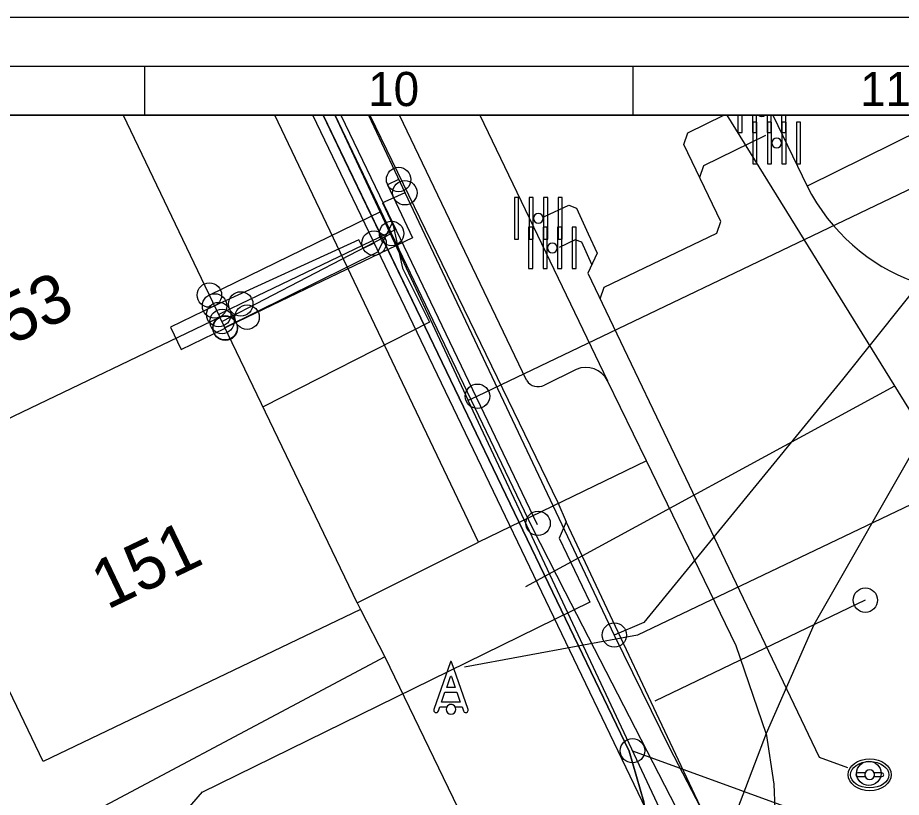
# Model space of a CAD drawing. Extents: x 192672 to 192910, y 446344 to 446512.
# Drawn here: x 192758.05 to 192776.14, y 446495.79 to 446511.76 of the extents above; entities that cross this region are included whole.
import ezdxf

# ---------------------------------------------------------------- set-up
doc = ezdxf.new("R2010")
doc.units = 0
for name, color, linetype in [('( Toegevoegd 29-11-2021 14_41_42) wegdeel vlak', 7, 'Continuous'), ('1010 viewport', 7, 'Continuous'), ('B-OI-KL-()_AFSLUITER_WATER-S', 7, 'Continuous'), ('B-OI-KL-()_OVERIG_RIOOLVRIJVERVAL-S', 7, 'Continuous'), ('B-OI-KL-()_PUNTVANLEVERING_WATER-S', 7, 'Continuous'), ('B-OI-KL-BUISLEIDING_OLIEGASCHEMICALIEN_GASLAGEDRUK-G', 7, 'Continuous'), ('B-OI-KL-DATA-G', 7, 'Continuous'), ('B-OI-KL-DATA_GTWP-S', 7, 'Continuous'), ('B-OI-KL-DATA_KABELBED-G', 7, 'Continuous'), ('B-OI-KL-DATA_MOF-S', 7, 'Continuous'), ('B-OI-KL-DATA_OVERIG-S', 7, 'Continuous'), ('B-OI-KL-ET_LS-G', 7, 'Continuous'), ('B-OI-KL-ET_LS_DELIVERYPOINT-S', 7, 'Continuous'), ('B-OI-KL-ET_LS_MOF-S', 7, 'Continuous'), ('B-OI-KL-GAS_LD_AFTAKZADEL-S', 7, 'Continuous'), ('B-OI-KL-GAS_LD_DELIVERYPOINT-S', 7, 'Continuous'), ('B-OI-KL-GAS_LD_EINDKAP-S', 7, 'Continuous'), ('B-OI-KL-GAS_LD_OVERGANGSSTUK-S', 7, 'Continuous'), ('B-OI-KL-GAS_LD_TSTUK-S', 7, 'Continuous'), ('B-OI-KL-WATER-G', 7, 'Continuous'), ('B-OI-RI-RIOOLVRIJVERVAL-G', 7, 'Continuous'), ('bovenleidingmast', 7, 'Continuous'), ('Default', 7, 'Continuous'), ('huisnummerreeks BGT', 7, 'Continuous'), ('inspectie-   rioolput', 7, 'Continuous'), ('kant open verharding', 7, 'Continuous'), ('kant verharding', 7, 'Continuous'), ('kolk', 7, 'Continuous'), ('pand op maaiveld vlak', 7, 'Continuous'), ('verkeerseiland - berm', 7, 'Continuous'), ('X-XX-AL-TEKENBLAD-S', 7, 'Continuous')]:
    doc.layers.add(name, color=color, linetype=linetype)

# ---------------------------------------------------------------- blocks, each defined once
blk = doc.blocks.new('B-OI-KL-GAS_LD_AFTAKZADEL-S')
at = {"layer": 'Default'}
blk.add_circle((0, 0), 0.25, dxfattribs=at)
blk = doc.blocks.new('B-OI-KL-GAS_LD_DELIVERYPOINT-S')
at = {"layer": 'Default'}
blk.add_circle((0, 0), 0.25, dxfattribs=at)
blk = doc.blocks.new('B-OI-KL-GAS_LD_EINDKAP-S')
at = {"layer": 'Default'}
blk.add_circle((0, 0), 0.25, dxfattribs=at)
blk = doc.blocks.new('B-OI-KL-GAS_LD_OVERGANGSSTUK-S')
at = {"layer": 'Default'}
blk.add_circle((0, 0), 0.25, dxfattribs=at)
blk = doc.blocks.new('B-OI-KL-GAS_LD_TSTUK-S')
at = {"layer": 'Default'}
blk.add_circle((0, 0), 0.25, dxfattribs=at)
blk = doc.blocks.new('B-OI-KL-ET_LS_DELIVERYPOINT-S')
at = {"layer": 'Default'}
blk.add_circle((0, 0), 0.25, dxfattribs=at)
blk = doc.blocks.new('B-OI-KL-ET_LS_MOF-S')
at = {"layer": 'Default'}
blk.add_circle((0, 0), 0.25, dxfattribs=at)
blk = doc.blocks.new('B-OI-KL-DATA_OVERIG-S')
at = {"layer": 'Default'}
blk.add_circle((0, 0), 0.25, dxfattribs=at)
blk = doc.blocks.new('B-OI-KL-()_OVERIG_RIOOLVRIJVERVAL-S')
at = {"layer": 'Default'}
blk.add_circle((0, 0), 0.25, dxfattribs=at)
blk = doc.blocks.new('B-OI-KL-()_AFSLUITER_WATER-S')
at = {"layer": 'Default'}
blk.add_circle((0, 0), 0.25, dxfattribs=at)
blk = doc.blocks.new('B-OI-KL-()_PUNTVANLEVERING_WATER-S')
at = {"layer": 'Default'}
blk.add_circle((0, 0), 0.25, dxfattribs=at)
blk = doc.blocks.new('B-OI-KL-DATA_GTWP-S')
at = {"layer": 'Default'}
blk.add_circle((0, 0), 0.25, dxfattribs=at)
blk = doc.blocks.new('B-OI-KL-DATA_MOF-S')
at = {"layer": 'Default'}
blk.add_circle((0, 0), 0.25, dxfattribs=at)

msp = doc.modelspace()

# ---------------------------------------------------------------- linework, layer by layer
at = {"layer": '( Toegevoegd 29-11-2021 14_41_42) wegdeel vlak'}
msp.add_lwpolyline([(192765.561, 446498.667), (192758.023, 446494.654), (192749.243, 446494.562), (192737.517, 446496.509), (192736.353, 446498.833), (192734.578, 446497.242), (192732.701, 446497.637), (192731.791, 446499.455)], dxfattribs=at)
at = {"layer": '1010 viewport'}
msp.add_lwpolyline([(192675.743, 446509.756), (192860.643, 446509.756), (192860.643, 446345.556), (192675.743, 446345.556)], close=True, dxfattribs=at)
at = {"layer": 'B-OI-KL-BUISLEIDING_OLIEGASCHEMICALIEN_GASLAGEDRUK-G'}
for points in [[(192765.227, 446509.756), (192766.142, 446507.813), (192770.261, 446499.113)], [(192779.213, 446509.327), (192778.681, 446509.051), (192774.928, 446504.345), (192770.865, 446499.368), (192770.261, 446499.113)], [(192765.846, 446508.441), (192765.62, 446508.335), (192766.133, 446507.248), (192762.745, 446505.622)], [(192765.974, 446508.17), (192765.748, 446508.063), (192765.517, 446507.966), (192765.779, 446507.411), (192762.615, 446505.893)], [(192762.615, 446505.893), (192762.164, 446505.676)], [(192762.745, 446505.622), (192762.294, 446505.406)], [(192775.398, 446499.827), (192771.09, 446497.758)], [(192770.261, 446499.113), (192771.393, 446496.803), (192772.556, 446494.554), (192770.877, 446489.886), (192758.67, 446457.345), (192745.084, 446421.436), (192742.217, 446413.618)]]:
    msp.add_lwpolyline(points, dxfattribs=at)
at = {"layer": 'B-OI-KL-DATA-G'}
for p in [(192764.73, 446508.869), (192764.741, 446508.846)]:
    msp.add_line(p, (192764.304, 446509.756), dxfattribs=at)
for points in [[(192764.304, 446509.756), (192770.565, 446496.734), (192770.867, 446495.7), (192770.986, 446494.71), (192770.973, 446493.522), (192770.841, 446492.782), (192768.74, 446486.807), (192749.794, 446435.599)], [(192764.304, 446509.756), (192770.565, 446496.734), (192770.867, 446495.7), (192770.986, 446494.71), (192770.973, 446493.522), (192770.841, 446492.782), (192768.74, 446486.807), (192749.794, 446435.599)], [(192764.304, 446509.756), (192770.565, 446496.734), (192770.867, 446495.7), (192770.986, 446494.71), (192770.973, 446493.522), (192770.841, 446492.782), (192768.74, 446486.807), (192749.794, 446435.599)], [(192764.304, 446509.756), (192770.565, 446496.734), (192770.867, 446495.7), (192770.986, 446494.71), (192770.973, 446493.522), (192770.841, 446492.782), (192768.74, 446486.807), (192749.794, 446435.599)], [(192764.304, 446509.756), (192770.565, 446496.734), (192770.867, 446495.7), (192770.986, 446494.71), (192770.973, 446493.522), (192770.841, 446492.782), (192768.74, 446486.807), (192749.794, 446435.599)], [(192764.304, 446509.756), (192770.565, 446496.734), (192770.867, 446495.7), (192770.986, 446494.71), (192770.973, 446493.522), (192770.841, 446492.782), (192768.74, 446486.807), (192749.794, 446435.599)], [(192764.304, 446509.756), (192770.565, 446496.734), (192770.867, 446495.7), (192770.986, 446494.71), (192770.973, 446493.522), (192770.841, 446492.782), (192768.74, 446486.807), (192749.794, 446435.599)], [(192764.304, 446509.756), (192770.565, 446496.734), (192770.867, 446495.7), (192770.986, 446494.71), (192770.973, 446493.522), (192770.841, 446492.782), (192768.74, 446486.807), (192749.794, 446435.599)], [(192764.304, 446509.756), (192770.565, 446496.734), (192770.867, 446495.7), (192770.986, 446494.71), (192770.973, 446493.522), (192770.841, 446492.782), (192768.74, 446486.807), (192749.794, 446435.599)], [(192764.304, 446509.756), (192770.565, 446496.734), (192770.867, 446495.7), (192770.986, 446494.71), (192770.973, 446493.522), (192770.841, 446492.782), (192768.74, 446486.807), (192749.794, 446435.599)], [(192764.304, 446509.756), (192770.565, 446496.734), (192770.867, 446495.7), (192770.986, 446494.71), (192770.973, 446493.522), (192770.841, 446492.782), (192768.74, 446486.807), (192749.794, 446435.599)], [(192764.304, 446509.756), (192770.565, 446496.734), (192770.867, 446495.7), (192770.986, 446494.71), (192770.973, 446493.522), (192770.841, 446492.782), (192768.74, 446486.807), (192749.794, 446435.599)], [(192764.304, 446509.756), (192770.565, 446496.734), (192770.867, 446495.7), (192770.986, 446494.71), (192770.973, 446493.522), (192770.841, 446492.782), (192768.74, 446486.807), (192749.794, 446435.599)], [(192764.304, 446509.756), (192770.565, 446496.734), (192770.867, 446495.7), (192770.986, 446494.71), (192770.973, 446493.522), (192770.841, 446492.782), (192768.74, 446486.807), (192749.794, 446435.599)], [(192764.304, 446509.756), (192770.565, 446496.734), (192770.867, 446495.7), (192770.986, 446494.71), (192770.973, 446493.522), (192770.841, 446492.782), (192768.74, 446486.807), (192749.794, 446435.599)], [(192764.304, 446509.756), (192770.565, 446496.734), (192770.867, 446495.7), (192770.986, 446494.71), (192770.973, 446493.522), (192770.841, 446492.782), (192768.74, 446486.807), (192770.369, 446486.306), (192778.924, 446483.081), (192784.343, 446497.176), (192794.941, 446502.078), (192809.504, 446508.873), (192809.089, 446509.756)], [(192764.304, 446509.756), (192770.565, 446496.734), (192770.867, 446495.7), (192770.986, 446494.71), (192770.973, 446493.522), (192770.841, 446492.782), (192768.74, 446486.807), (192770.369, 446486.306), (192778.924, 446483.081), (192784.343, 446497.176), (192794.941, 446502.078), (192809.504, 446508.873), (192809.089, 446509.756)], [(192768.74, 446486.807), (192770.841, 446492.782), (192770.973, 446493.522), (192770.986, 446494.71), (192770.867, 446495.7), (192770.565, 446496.734), (192764.304, 446509.756)], [(192768.74, 446486.807), (192770.841, 446492.782), (192770.973, 446493.522), (192770.986, 446494.71), (192770.867, 446495.7), (192770.565, 446496.734), (192764.304, 446509.756)], [(192764.304, 446509.756), (192770.565, 446496.734), (192770.867, 446495.7), (192770.986, 446494.71), (192770.973, 446493.522), (192770.841, 446492.782), (192768.74, 446486.807)], [(192764.304, 446509.756), (192770.565, 446496.734), (192770.867, 446495.7), (192770.986, 446494.71), (192770.973, 446493.522), (192770.841, 446492.782), (192768.74, 446486.807)], [(192764.664, 446509.756), (192765.718, 446507.559), (192768.684, 446501.379)], [(192765.718, 446507.559), (192765.412, 446506.952), (192762.293, 446505.411)], [(192765.718, 446507.559), (192765.924, 446506.626), (192766.433, 446505.613), (192766.478, 446505.523), (192763.072, 446503.788)]]:
    msp.add_lwpolyline(points, dxfattribs=at)
at = {"layer": 'B-OI-KL-DATA_KABELBED-G'}
msp.add_line((192764.73, 446508.869), (192764.304, 446509.756), dxfattribs=at)
for points in [[(192771.773, 446495.105), (192769.257, 446500), (192768.58, 446501.319), (192765.703, 446507.336), (192765.488, 446507.787), (192764.547, 446509.756)], [(192764.741, 446508.846), (192764.73, 446508.869)], [(192767.214, 446503.702), (192764.741, 446508.846)], [(192765.703, 446507.336), (192765.488, 446507.787), (192761.973, 446506.075)], [(192765.703, 446507.336), (192762.232, 446505.534)], [(192768.74, 446486.807), (192770.841, 446492.782), (192770.973, 446493.522), (192770.986, 446494.71), (192770.867, 446495.7), (192770.565, 446496.734), (192767.214, 446503.702)]]:
    msp.add_lwpolyline(points, dxfattribs=at)
at = {"layer": 'B-OI-KL-ET_LS-G'}
for points in [[(192774.175, 446493.36), (192772.308, 446492.626), (192764.089, 446509.756)], [(192765.26, 446509.756), (192769.107, 446501.83), (192769.274, 446501.433)], [(192807.795, 446509.756), (192785.465, 446499.231), (192784.279, 446497.948), (192782.198, 446492.212), (192772.784, 446495.238), (192772.082, 446495.48), (192769.274, 446501.433)], [(192765.344, 446507.138), (192765.119, 446507.03), (192765.034, 446507.207), (192762.079, 446505.853)], [(192762.079, 446505.853), (192761.178, 446505.42), (192761.397, 446504.963), (192762.299, 446505.395)], [(192769.274, 446501.433), (192769.129, 446501.094), (192769.758, 446499.788), (192761.82, 446495.891)], [(192738.378, 446496.142), (192739.482, 446495.624), (192753.92, 446493.148), (192759.346, 446493.622), (192761.266, 446495.244), (192761.834, 446495.904)]]:
    msp.add_lwpolyline(points, dxfattribs=at)
at = {"layer": 'B-OI-KL-WATER-G'}
for p, q in [((192764.542, 446509.756), (192767.273, 446503.913)), ((192779.457, 446509.756), (192767.46, 446504.003))]:
    msp.add_line(p, q, dxfattribs=at)
for points in [[(192767.46, 446504.003), (192767.273, 446503.913)], [(192771.346, 446495.222), (192767.273, 446503.913)], [(192770.633, 446496.744), (192785.879, 446491.187)]]:
    msp.add_lwpolyline(points, dxfattribs=at)
at = {"layer": 'B-OI-RI-RIOOLVRIJVERVAL-G'}
msp.add_line((192779.05, 446499.28), (192772.573, 446509.756), dxfattribs=at)
for points in [[(192769.97, 446506.001), (192770.05, 446506.238), (192772.36, 446507.344), (192772.441, 446507.58), (192771.684, 446509.159), (192771.764, 446509.396), (192772.501, 446509.756)], [(192773.356, 446509.342), (192772.086, 446508.721), (192772.007, 446508.484)], [(192768.83, 446507.682), (192769.327, 446507.913), (192769.486, 446507.854), (192769.729, 446507.328), (192769.91, 446506.935), (192769.722, 446506.521)], [(192769.804, 446506.701), (192769.595, 446507.156), (192769.462, 446507.205), (192769.133, 446507.047)], [(192769.722, 446506.521), (192774.454, 446496.61), (192775.036, 446496.398)], [(192775.996, 446504.211), (192768.444, 446500.097)], [(192777.234, 446502.213), (192770.738, 446499.109), (192767.197, 446498.456)]]:
    msp.add_lwpolyline(points, dxfattribs=at)
at = {"layer": 'bovenleidingmast'}
for p, q in [((192766.908, 446498.564), (192766.567, 446497.591)), ((192767.267, 446497.591), (192766.926, 446498.564))]:
    msp.add_line(p, q, dxfattribs=at)
for points in [[(192766.926, 446498.261), (192767.004, 446498.041), (192766.83, 446498.041), (192766.908, 446498.261)], [(192766.661, 446497.558), (192766.69, 446497.641), (192766.83, 446497.641)], [(192767.004, 446497.641), (192767.144, 446497.641), (192767.173, 446497.558)]]:
    msp.add_lwpolyline(points, dxfattribs=at)
msp.add_lwpolyline([(192767.039, 446497.941), (192767.109, 446497.741), (192766.725, 446497.741), (192766.795, 446497.941)], close=True, dxfattribs=at)
for centre, radius, start, end in [((192766.917, 446498.561), 0.01, 19.29, 160.71), ((192766.917, 446498.258), 0.01, 19.29, 160.71), ((192766.917, 446497.591), 0.1, 0, 180), ((192766.917, 446497.591), 0.1, 30, 150), ((192766.614, 446497.574), 0.05, 160.71, 340.71), ((192766.917, 446497.591), 0.1, 180, 0), ((192767.22, 446497.574), 0.05, 199.29, 19.29)]:
    msp.add_arc(centre, radius, start, end, dxfattribs=at)
at = {"layer": 'inspectie-   rioolput'}
for p, q in [((192775.395, 446496.29), (192775.238, 446496.29)), ((192775.238, 446496.215), (192775.395, 446496.215)), ((192775.738, 446496.29), (192775.581, 446496.29)), ((192775.581, 446496.215), (192775.738, 446496.215))]:
    msp.add_line(p, q, dxfattribs=at)
for centre, radius, start, end in [((192775.238, 446496.252), 0.0375, 90, 270), ((192775.488, 446496.252), 0.1, 0, 180), ((192775.488, 446496.252), 0.1, 157.9757, 180), ((192775.488, 446496.252), 0.1, 180, 202.0243), ((192775.488, 446496.252), 0.1, 180, 0), ((192775.488, 446496.252), 0.1, 0, 22.0243), ((192775.488, 446496.252), 0.1, 337.9757, 0), ((192775.738, 446496.252), 0.0375, 270, 90)]:
    msp.add_arc(centre, radius, start, end, dxfattribs=at)
for major_axis, ratio in [((-0.442, 0), 0.73911), ((-0.392, 0), 0.689655)]:
    msp.add_ellipse((192775.488, 446496.252), major_axis=major_axis, ratio=ratio, dxfattribs=at)
at = {"layer": 'kant open verharding'}
for p, q in [((192767.483, 446501.015), (192763.311, 446509.756)), ((192770.917, 446502.682), (192770.122, 446504.32)), ((192770.917, 446502.682), (192767.483, 446501.015)), ((192764.996, 446499.775), (192767.483, 446501.015)), ((192765.063, 446499.636), (192765.561, 446498.667))]:
    msp.add_line(p, q, dxfattribs=at)
for points in [[(192781.115, 446507.223), (192778.58, 446505.448), (192776.532, 446503.157), (192774.342, 446499.324), (192773.367, 446497.097)], [(192773.367, 446497.097), (192772.756, 446498.895), (192770.917, 446502.682)], [(192765.561, 446498.667), (192769.255, 446491.03), (192768.995, 446490.291)]]:
    msp.add_lwpolyline(points, dxfattribs=at)
msp.add_arc((192777.798, 446510.118), 4.023, 206.7487, 292.6943, dxfattribs=at)
at = {"layer": 'kant verharding'}
for p, q in [((192768.466, 446504.33), (192765.861, 446509.756)), ((192767.511, 446509.756), (192770.122, 446504.32)), ((192769.48, 446504.551), (192768.83, 446504.229))]:
    msp.add_line(p, q, dxfattribs=at)
for centre, radius, start, end in [((192769.681, 446504.102), 0.492, 26.3279, 114.0934), ((192768.702, 446504.475), 0.277, 211.574, 297.4102)]:
    msp.add_arc(centre, radius, start, end, dxfattribs=at)
at = {"layer": 'kolk'}
msp.add_line((192773.345, 446509.756), (192773.215, 446509.756), dxfattribs=at)
for points in [[(192772.876, 446509.756), (192772.791, 446509.756), (192772.791, 446509.407), (192772.876, 446509.407)], [(192773.174, 446509.756), (192773.089, 446509.756), (192773.089, 446509.407), (192773.174, 446509.407)], [(192773.471, 446509.756), (192773.386, 446509.756), (192773.386, 446509.407), (192773.471, 446509.407)], [(192773.769, 446509.756), (192773.684, 446509.756), (192773.684, 446509.407), (192773.769, 446509.407)], [(192773.181, 446509.19), (192773.181, 446509.615), (192773.096, 446509.615), (192773.096, 446509.19), (192773.096, 446508.765), (192773.181, 446508.765)], [(192773.479, 446509.19), (192773.479, 446509.615), (192773.394, 446509.615), (192773.394, 446509.19), (192773.394, 446508.765), (192773.479, 446508.765)], [(192773.776, 446509.19), (192773.776, 446509.615), (192773.691, 446509.615), (192773.691, 446509.19), (192773.691, 446508.765), (192773.776, 446508.765)], [(192774.074, 446509.19), (192774.074, 446509.615), (192773.989, 446509.615), (192773.989, 446509.19), (192773.989, 446508.765), (192774.074, 446508.765)], [(192768.302, 446507.647), (192768.302, 446508.072), (192768.217, 446508.072), (192768.217, 446507.647), (192768.217, 446507.222), (192768.302, 446507.222)], [(192768.6, 446507.647), (192768.6, 446508.072), (192768.515, 446508.072), (192768.515, 446507.647), (192768.515, 446507.222), (192768.6, 446507.222)], [(192768.897, 446507.647), (192768.897, 446508.072), (192768.812, 446508.072), (192768.812, 446507.647), (192768.812, 446507.222), (192768.897, 446507.222)], [(192769.195, 446507.647), (192769.195, 446508.072), (192769.11, 446508.072), (192769.11, 446507.647), (192769.11, 446507.222), (192769.195, 446507.222)], [(192768.59, 446507.041), (192768.59, 446507.466), (192768.505, 446507.466), (192768.505, 446507.041), (192768.505, 446506.616), (192768.59, 446506.616)], [(192768.888, 446507.041), (192768.888, 446507.466), (192768.803, 446507.466), (192768.803, 446507.041), (192768.803, 446506.616), (192768.888, 446506.616)], [(192769.185, 446507.041), (192769.185, 446507.466), (192769.1, 446507.466), (192769.1, 446507.041), (192769.1, 446506.616), (192769.185, 446506.616)], [(192769.483, 446507.041), (192769.483, 446507.466), (192769.398, 446507.466), (192769.398, 446507.041), (192769.398, 446506.616), (192769.483, 446506.616)]]:
    msp.add_lwpolyline(points, close=True, dxfattribs=at)
for centre, start, end in [((192773.28, 446509.832), 229.7441, 310.2559), ((192773.585, 446509.19), 0, 180), ((192773.585, 446509.19), 180, 0), ((192768.706, 446507.647), 0, 180), ((192768.706, 446507.647), 180, 0), ((192768.994, 446507.041), 0, 180), ((192768.994, 446507.041), 180, 0)]:
    msp.add_arc(centre, 0.1, start, end, dxfattribs=at)
at = {"layer": 'pand op maaiveld vlak'}
for p, q in [((192760.207, 446509.756), (192762.189, 446505.624)), ((192755.698, 446502.509), (192762.189, 446505.624)), ((192764.996, 446499.775), (192762.189, 446505.624)), ((192764.996, 446499.775), (192765.063, 446499.636))]:
    msp.add_line(p, q, dxfattribs=at)
msp.add_lwpolyline([(192765.063, 446499.636), (192758.571, 446496.521), (192755.698, 446502.509)], dxfattribs=at)
at = {"layer": 'verkeerseiland - berm'}
for p in [(192773.502, 446509.756), (192777.138, 446509.756)]:
    msp.add_line(p, (192774.205, 446508.307), dxfattribs=at)
for points in [[(192773.367, 446497.097), (192771.694, 446492.7), (192769.851, 446487.804), (192770.692, 446487.472)], [(192773.367, 446497.097), (192773.526, 446496.058), (192773.566, 446495.048), (192773.494, 446493.942), (192773.307, 446493.007), (192770.985, 446486.905)]]:
    msp.add_lwpolyline(points, dxfattribs=at)
at = {"layer": 'X-XX-AL-TEKENBLAD-S'}
for p, q in [((192909.543, 446511.756), (192671.743, 446511.756)), ((192908.543, 446510.756), (192674.743, 446510.756)), ((192760.643, 446510.756), (192760.643, 446509.756)), ((192770.643, 446510.756), (192770.643, 446509.756))]:
    msp.add_line(p, q, dxfattribs=at)
msp.add_lwpolyline([(192675.743, 446345.556), (192907.543, 446345.556), (192907.543, 446509.756), (192675.743, 446509.756)], close=True, dxfattribs=at)

# ---------------------------------------------------------------- block references
at = {"layer": 'B-OI-KL-()_AFSLUITER_WATER-S'}
msp.add_blockref('B-OI-KL-()_AFSLUITER_WATER-S', (192767.46, 446504.003), dxfattribs=at)
at = {"layer": 'B-OI-KL-()_OVERIG_RIOOLVRIJVERVAL-S'}
msp.add_blockref('B-OI-KL-()_OVERIG_RIOOLVRIJVERVAL-S', (192775.47, 446496.28), dxfattribs=at)
at = {"layer": 'B-OI-KL-()_PUNTVANLEVERING_WATER-S'}
msp.add_blockref('B-OI-KL-()_PUNTVANLEVERING_WATER-S', (192770.633, 446496.744), dxfattribs=at)
at = {"layer": 'B-OI-KL-DATA_GTWP-S'}
for p in [(192765.703, 446507.336), (192765.703, 446507.336), (192761.973, 446506.075), (192762.232, 446505.534)]:
    msp.add_blockref('B-OI-KL-DATA_GTWP-S', p, dxfattribs=at)
at = {"layer": 'B-OI-KL-DATA_MOF-S'}
msp.add_blockref('B-OI-KL-DATA_MOF-S', (192765.703, 446507.336), dxfattribs=at)
at = {"layer": 'B-OI-KL-DATA_OVERIG-S'}
msp.add_blockref('B-OI-KL-DATA_OVERIG-S', (192768.7, 446501.4), dxfattribs=at)
at = {"layer": 'B-OI-KL-ET_LS_DELIVERYPOINT-S'}
for p in [(192762.079, 446505.853), (192762.299, 446505.395)]:
    msp.add_blockref('B-OI-KL-ET_LS_DELIVERYPOINT-S', p, dxfattribs=at)
at = {"layer": 'B-OI-KL-ET_LS_MOF-S'}
msp.add_blockref('B-OI-KL-ET_LS_MOF-S', (192765.344, 446507.138), dxfattribs=at)
at = {"layer": 'B-OI-KL-GAS_LD_AFTAKZADEL-S'}
for p in [(192765.846, 446508.441), (192765.974, 446508.17)]:
    msp.add_blockref('B-OI-KL-GAS_LD_AFTAKZADEL-S', p, dxfattribs=at)
at = {"layer": 'B-OI-KL-GAS_LD_DELIVERYPOINT-S'}
for p in [(192762.164, 446505.676), (192762.294, 446505.406)]:
    msp.add_blockref('B-OI-KL-GAS_LD_DELIVERYPOINT-S', p, dxfattribs=at)
at = {"layer": 'B-OI-KL-GAS_LD_EINDKAP-S'}
msp.add_blockref('B-OI-KL-GAS_LD_EINDKAP-S', (192775.398, 446499.827), dxfattribs=at)
at = {"layer": 'B-OI-KL-GAS_LD_OVERGANGSSTUK-S'}
for p in [(192762.615, 446505.893), (192762.745, 446505.622)]:
    msp.add_blockref('B-OI-KL-GAS_LD_OVERGANGSSTUK-S', p, dxfattribs=at)
at = {"layer": 'B-OI-KL-GAS_LD_TSTUK-S'}
msp.add_blockref('B-OI-KL-GAS_LD_TSTUK-S', (192770.261, 446499.113), dxfattribs=at)

# ---------------------------------------------------------------- texts
at = {"layer": 'huisnummerreeks BGT'}
for s, p in [('153', (192757.254, 446504.724)), ('151', (192759.881, 446499.624))]:
    msp.add_text(s, height=1, rotation=25.6, dxfattribs=at).set_placement(p)
at = {"layer": 'X-XX-AL-TEKENBLAD-S'}
for s, p in [('10', (192765.224, 446509.945)), ('11', (192775.293, 446509.945))]:
    msp.add_text(s, height=0.7, dxfattribs=at).set_placement(p)

doc.saveas('drawing.dxf')
